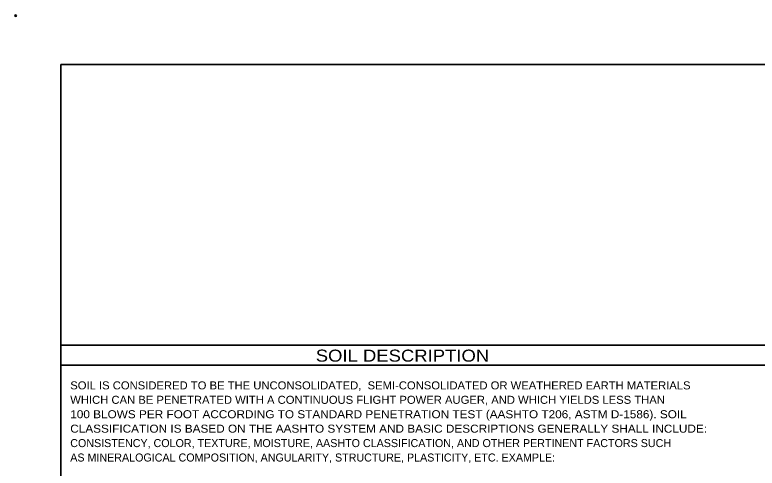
# Model space of a CAD drawing. Extents: x 2137492.6 to 2137529.1, y 2137475.8 to 2137563.
# Drawn here: x 2137492.6 to 2137501.87, y 2137556.68 to 2137562.34 of the extents above; entities that cross this region are included whole.
import ezdxf

# ---------------------------------------------------------------- set-up
doc = ezdxf.new("R2010")
doc.units = 0
doc.header["$LTSCALE"] = 0.04
doc.header["$PDMODE"] = 32
doc.header["$PDSIZE"] = 0.02
doc.layers.add('1', color=7, linetype='Continuous', lineweight=35)

msp = doc.modelspace()

# ---------------------------------------------------------------- linework, layer by layer
at = {"layer": '1'}
for p, q in [((2137493.171, 2137561.718), (2137528.371, 2137561.718)), ((2137493.171, 2137558.218), (2137528.371, 2137558.218)), ((2137493.171, 2137557.968), (2137528.371, 2137557.968))]:
    msp.add_line(p, q, dxfattribs=at)
msp.add_lwpolyline([(2137493.171, 2137561.718), (2137493.171, 2137539.727), (2137528.371, 2137539.727)], dxfattribs=at)
msp.add_point((2137492.607, 2137562.328), dxfattribs=at)

# ---------------------------------------------------------------- texts
for s, height, width, p in [('SOIL DESCRIPTION', 0.15, 1.15, (2137496.355, 2137558.011)), ('SOIL IS CONSIDERED TO BE THE UNCONSOLIDATED,  SEMI-CONSOLIDATED OR WEATHERED EARTH MATERIALS ', 0.1, 1.05, (2137493.289, 2137557.665)), ('WHICH CAN BE PENETRATED WITH A CONTINUOUS FLIGHT POWER AUGER, AND WHICH YIELDS LESS THAN ', 0.1, 1.05, (2137493.289, 2137557.485)), ('100 BLOWS PER FOOT ACCORDING TO STANDARD PENETRATION TEST (AASHTO T206, ASTM D-1586). SOIL ', 0.1, 1.1, (2137493.289, 2137557.305)), ('CLASSIFICATION IS BASED ON THE AASHTO SYSTEM AND BASIC DESCRIPTIONS GENERALLY SHALL INCLUDE:', 0.1, 1.1, (2137493.289, 2137557.125))]:
    msp.add_text(s, height=height, dxfattribs=dict(at, width=width)).set_placement(p)
for s, p in [('CONSISTENCY, COLOR, TEXTURE, MOISTURE, AASHTO CLASSIFICATION, AND OTHER PERTINENT FACTORS SUCH ', (2137493.289, 2137556.945)), ('AS MINERALOGICAL COMPOSITION, ANGULARITY, STRUCTURE, PLASTICITY, ETC. EXAMPLE:', (2137493.289, 2137556.765))]:
    msp.add_text(s, height=0.1, dxfattribs=at).set_placement(p)

doc.saveas('drawing.dxf')
